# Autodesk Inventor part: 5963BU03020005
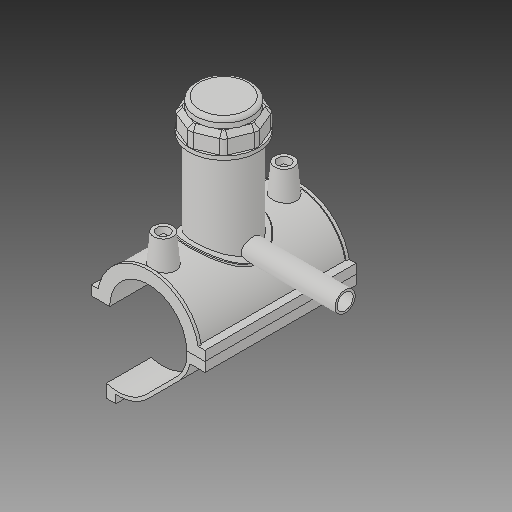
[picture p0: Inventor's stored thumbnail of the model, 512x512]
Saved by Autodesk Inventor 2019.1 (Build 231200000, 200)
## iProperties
Created: 2017-07
Part Number: 5963BU03020005
Material: Generic
Description: PLASSON TAPPING SADDLE 2''IPS x 1 1/2''CTS
Document SubType Name: Modeling
Designer: KIM
Mass: 1712.7 g
Surface Area: 2671.49 cm^2
Volume: 1712.7 cm^3
Density: 1 g/cm^3
Appearance: Default
Author: KIM
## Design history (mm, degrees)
derived "5963B.ipt"
feature "Solid1::5963B.ipt"
feature "Solid2::5963B.ipt"
feature "Solid4::5963B.ipt"
feature "Solid5::5963B.ipt"
tag "TaggingFeature1"
body "Solid1"
body "Solid2"
other parameters: "d0" = 60.1, "d2" = 88.9, "d3" = 15.025, "d4" = 118.11, "d5" = 0, "d6" = 0.1, "d8" = 0, "d19" = 6, "d20" = 6, "d21" = 70.866, "d23" = 0, "d24" = 35.433, "d26" = 0, "d29" = 3, "d30" = 20.03333, "d31" = 6, "d32" = 0, "d33" = 0, "d34" = 0.6, "d40" = 40.6276, "d41" = 54.09, "d43" = 0, "d45" = 0, "d47" = 109.931, "d70" = 15, "d72" = 0, "d73" = 6, "d75" = 5, "d76" = 0, "d77" = 3.005, "d78" = 60.05, "d79" = 15, "d80" = 47.244, "d82" = 5 deg, "d84" = 4, "d85" = 14, "d86" = 0, "d87" = 3, "d88" = 0, "d89" = 1, "d90" = 1, "d91" = 94.488, "d92" = 0, "d93" = 0.5, "d94" = 31.63158, "d96" = 79.6926, "d97" = 2.3622, "d98" = 0, "d102" = 0.601, "d120" = 140 deg, "d121" = 24.228, "d122" = 20 deg, "d123" = 156.26, "d124" = 46.878, "d126" = 0, "d143" = 61.903, "d145" = 13.86923, "d149" = 0.9015, "d150" = 15.25615, "d153" = 118.11, "d154" = 0, "d156" = 39.065, "d157" = 160 deg, "d159" = 3.606, "d161" = 0.9015, "d162" = 70.866, "d163" = 0, "d164" = 30.05, "d167" = 6.01, "d168" = 38.1122, "d170" = 3.2805, "d172" = 0, "d173" = 1, "d175" = 30.05, "d176" = 20 deg, "d177" = 4.207, "d178" = 18.03, "d180" = 0, "d183" = 7.212, "d184" = 3.3656, "d185" = 38.38575, "d186" = 38.38575, "d187" = 39.065, "d188" = 5.409, "d189" = 4.207, "d190" = 0, "d191" = 58.5975, "d193" = 6.1236, "d194" = 4.13385, "d195" = 90 deg, "d197" = 0, "d199" = 0, "d200" = 9.015, "d202" = 0, "d203" = 98.044, "d204" = 51.3855, "d205" = 37.863, "d206" = 45.9765, "d207" = 73.533, "d208" = 76.47432, "d209" = 91.18092, "d210" = 46.5174, "d211" = 54.09, "d212" = 43.272, "d213" = -1.395, "d216" = 0, "d217" = 6.01, "d218" = 3.005, "d219" = 0.601, "d222" = 60.1, "d224" = 0, "d230" = 3.606, "d233" = 6, "d236" = 44.45, "d237" = 35.433, "d238" = 6.02433, "d240" = 35.433, "d241" = 35.433, "d242" = 35.433, "d243" = 6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
